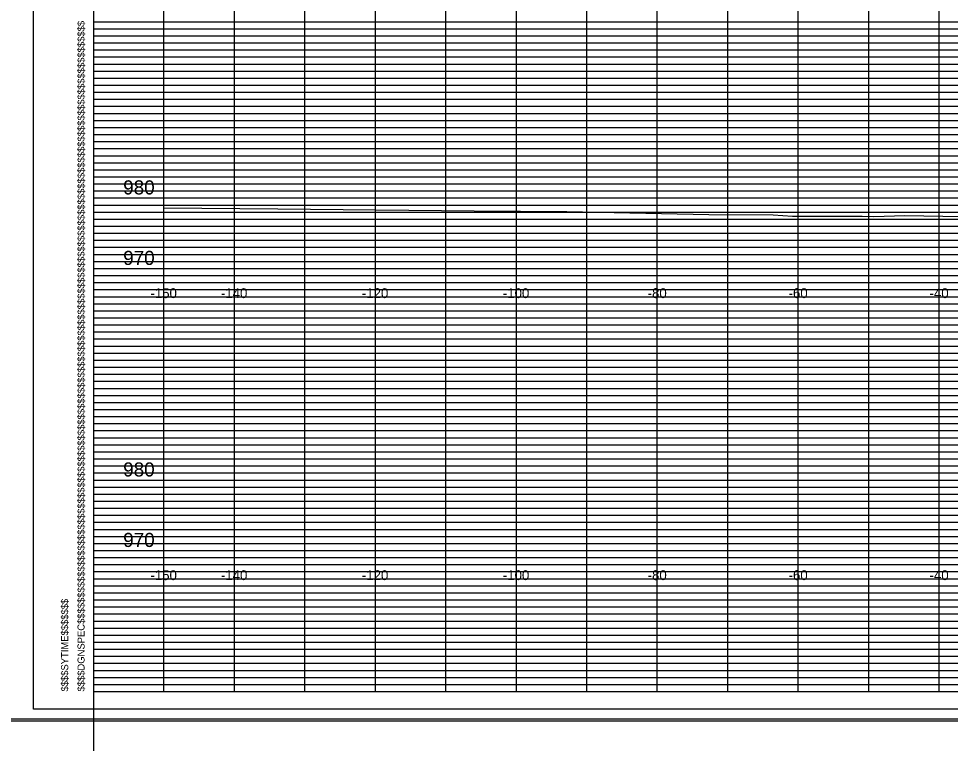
# Model space of a CAD drawing. Extents: x 2313580 to 2322968, y 282099 to 303247.
# Drawn here: x 2315288.3 to 2315420.5, y 285088.8 to 285191.6 of the extents above; entities that cross this region are included whole.
import ezdxf

# ---------------------------------------------------------------- set-up
doc = ezdxf.new("R2010")
doc.units = 0
for name, color, linetype in [('DESIGN - SCRATCH - User 1', 7, 'Continuous'), ('DESIGN - SHEET - Corner Text', 7, 'Continuous'), ('DESIGN - SHEET - Light Grid', 7, 'Continuous'), ('DESIGN - SHEET - Linework', 7, 'Continuous'), ('DESIGN - SHEET - Plot Shape', 7, 'Continuous'), ('DESIGN - TYPICAL - Text', 7, 'Continuous'), ('SURVEY - GROUND - Top of Ground', 7, 'Continuous')]:
    doc.layers.add(name, color=color, linetype=linetype)

msp = doc.modelspace()

# ---------------------------------------------------------------- linework, layer by layer
at = {"layer": 'DESIGN - SCRATCH - User 1'}
msp.add_line((2315298.88, 287582.67), (2315298.88, 284487.81), dxfattribs=at)
at = {"layer": 'DESIGN - SHEET - Light Grid'}
for p, q in [((2315298.88, 285191.13), (2315378.88, 285191.13)), ((2315378.88, 285191.13), (2315458.88, 285191.13)), ((2315298.88, 285190.13), (2315378.88, 285190.13)), ((2315378.88, 285190.13), (2315458.88, 285190.13)), ((2315298.88, 285189.13), (2315378.88, 285189.13)), ((2315378.88, 285189.13), (2315458.88, 285189.13)), ((2315298.88, 285188.13), (2315378.88, 285188.13)), ((2315298.88, 285187.13), (2315378.88, 285187.13)), ((2315378.88, 285188.13), (2315458.88, 285188.13)), ((2315378.88, 285187.13), (2315458.88, 285187.13)), ((2315298.88, 285185.13), (2315378.88, 285185.13)), ((2315378.88, 285185.13), (2315458.88, 285185.13)), ((2315298.88, 285184.13), (2315378.88, 285184.13)), ((2315298.88, 285183.13), (2315378.88, 285183.13)), ((2315378.88, 285184.13), (2315458.88, 285184.13)), ((2315378.88, 285183.13), (2315458.88, 285183.13)), ((2315298.88, 285182.13), (2315378.88, 285182.13)), ((2315378.88, 285182.13), (2315458.88, 285182.13)), ((2315298.88, 285181.13), (2315378.88, 285181.13)), ((2315378.88, 285181.13), (2315458.88, 285181.13)), ((2315298.88, 285180.13), (2315378.88, 285180.13)), ((2315298.88, 285179.13), (2315378.88, 285179.13)), ((2315378.88, 285180.13), (2315458.88, 285180.13)), ((2315378.88, 285179.13), (2315458.88, 285179.13)), ((2315298.88, 285178.13), (2315378.88, 285178.13)), ((2315378.88, 285178.13), (2315458.88, 285178.13)), ((2315298.88, 285177.13), (2315378.88, 285177.13)), ((2315378.88, 285177.13), (2315458.88, 285177.13)), ((2315298.88, 285175.13), (2315378.88, 285175.13)), ((2315378.88, 285175.13), (2315458.88, 285175.13)), ((2315298.88, 285174.13), (2315378.88, 285174.13)), ((2315378.88, 285174.13), (2315458.88, 285174.13)), ((2315298.88, 285173.13), (2315378.88, 285173.13)), ((2315378.88, 285173.13), (2315458.88, 285173.13)), ((2315298.88, 285172.13), (2315378.88, 285172.13)), ((2315298.88, 285171.13), (2315378.88, 285171.13)), ((2315378.88, 285172.13), (2315458.88, 285172.13)), ((2315378.88, 285171.13), (2315458.88, 285171.13)), ((2315298.88, 285170.13), (2315378.88, 285170.13)), ((2315378.88, 285170.13), (2315458.88, 285170.13)), ((2315298.88, 285169.13), (2315378.88, 285169.13)), ((2315378.88, 285169.13), (2315458.88, 285169.13)), ((2315298.88, 285168.13), (2315378.88, 285168.13)), ((2315298.88, 285167.13), (2315378.88, 285167.13)), ((2315378.88, 285168.13), (2315458.88, 285168.13)), ((2315378.88, 285167.13), (2315458.88, 285167.13)), ((2315298.88, 285165.13), (2315378.88, 285165.13)), ((2315378.88, 285165.13), (2315458.88, 285165.13)), ((2315298.88, 285164.13), (2315378.88, 285164.13)), ((2315298.88, 285163.13), (2315378.88, 285163.13)), ((2315378.88, 285164.13), (2315458.88, 285164.13)), ((2315378.88, 285163.13), (2315458.88, 285163.13)), ((2315298.88, 285162.13), (2315378.88, 285162.13)), ((2315378.88, 285162.13), (2315458.88, 285162.13)), ((2315298.88, 285161.13), (2315378.88, 285161.13)), ((2315378.88, 285161.13), (2315458.88, 285161.13)), ((2315298.88, 285160.13), (2315378.88, 285160.13)), ((2315298.88, 285159.13), (2315378.88, 285159.13)), ((2315378.88, 285160.13), (2315458.88, 285160.13)), ((2315378.88, 285159.13), (2315458.88, 285159.13)), ((2315298.88, 285158.13), (2315378.88, 285158.13)), ((2315378.88, 285158.13), (2315458.88, 285158.13)), ((2315298.88, 285157.13), (2315378.88, 285157.13)), ((2315378.88, 285157.13), (2315458.88, 285157.13)), ((2315298.88, 285155.13), (2315378.88, 285155.13)), ((2315378.88, 285155.13), (2315458.88, 285155.13)), ((2315298.88, 285154.13), (2315378.88, 285154.13)), ((2315378.88, 285154.13), (2315458.88, 285154.13)), ((2315298.88, 285153.13), (2315378.88, 285153.13)), ((2315378.88, 285153.13), (2315458.88, 285153.13)), ((2315298.88, 285152.13), (2315378.88, 285152.13)), ((2315298.88, 285151.13), (2315378.88, 285151.13)), ((2315378.88, 285152.13), (2315458.88, 285152.13)), ((2315378.88, 285151.13), (2315458.88, 285151.13)), ((2315298.88, 285150.13), (2315378.88, 285150.13)), ((2315378.88, 285150.13), (2315458.88, 285150.13)), ((2315298.88, 285149.13), (2315378.88, 285149.13)), ((2315378.88, 285149.13), (2315458.88, 285149.13)), ((2315298.88, 285148.13), (2315378.88, 285148.13)), ((2315378.88, 285148.13), (2315458.88, 285148.13)), ((2315298.88, 285147.13), (2315378.88, 285147.13)), ((2315378.88, 285147.13), (2315458.88, 285147.13)), ((2315298.88, 285145.13), (2315378.88, 285145.13)), ((2315378.88, 285145.13), (2315458.88, 285145.13)), ((2315298.88, 285144.13), (2315378.88, 285144.13)), ((2315378.88, 285144.13), (2315458.88, 285144.13)), ((2315298.88, 285143.13), (2315378.88, 285143.13)), ((2315298.88, 285142.13), (2315378.88, 285142.13)), ((2315378.88, 285143.13), (2315458.88, 285143.13)), ((2315378.88, 285142.13), (2315458.88, 285142.13)), ((2315298.88, 285141.13), (2315378.88, 285141.13)), ((2315378.88, 285141.13), (2315458.88, 285141.13)), ((2315298.88, 285140.13), (2315378.88, 285140.13)), ((2315378.88, 285140.13), (2315458.88, 285140.13)), ((2315298.88, 285139.13), (2315378.88, 285139.13)), ((2315298.88, 285138.13), (2315378.88, 285138.13)), ((2315378.88, 285139.13), (2315458.88, 285139.13)), ((2315378.88, 285138.13), (2315458.88, 285138.13)), ((2315298.88, 285137.13), (2315378.88, 285137.13)), ((2315378.88, 285137.13), (2315458.88, 285137.13)), ((2315298.88, 285135.13), (2315378.88, 285135.13)), ((2315298.88, 285134.13), (2315378.88, 285134.13)), ((2315378.88, 285135.13), (2315458.88, 285135.13)), ((2315378.88, 285134.13), (2315458.88, 285134.13)), ((2315298.88, 285133.13), (2315378.88, 285133.13)), ((2315378.88, 285133.13), (2315458.88, 285133.13)), ((2315298.88, 285132.13), (2315378.88, 285132.13)), ((2315378.88, 285132.13), (2315458.88, 285132.13)), ((2315298.88, 285131.13), (2315378.88, 285131.13)), ((2315298.88, 285130.13), (2315378.88, 285130.13)), ((2315378.88, 285131.13), (2315458.88, 285131.13)), ((2315378.88, 285130.13), (2315458.88, 285130.13)), ((2315298.88, 285129.13), (2315378.88, 285129.13)), ((2315378.88, 285129.13), (2315458.88, 285129.13)), ((2315298.88, 285128.13), (2315378.88, 285128.13)), ((2315378.88, 285128.13), (2315458.88, 285128.13)), ((2315298.88, 285127.13), (2315378.88, 285127.13)), ((2315378.88, 285127.13), (2315458.88, 285127.13)), ((2315298.88, 285125.13), (2315378.88, 285125.13)), ((2315378.88, 285125.13), (2315458.88, 285125.13)), ((2315298.88, 285124.13), (2315378.88, 285124.13)), ((2315378.88, 285124.13), (2315458.88, 285124.13)), ((2315298.88, 285123.13), (2315378.88, 285123.13)), ((2315298.88, 285122.13), (2315378.88, 285122.13)), ((2315378.88, 285123.13), (2315458.88, 285123.13)), ((2315378.88, 285122.13), (2315458.88, 285122.13)), ((2315298.88, 285121.13), (2315378.88, 285121.13)), ((2315378.88, 285121.13), (2315458.88, 285121.13)), ((2315298.88, 285120.13), (2315378.88, 285120.13)), ((2315378.88, 285120.13), (2315458.88, 285120.13)), ((2315298.88, 285119.13), (2315378.88, 285119.13)), ((2315298.88, 285118.13), (2315378.88, 285118.13)), ((2315378.88, 285119.13), (2315458.88, 285119.13)), ((2315378.88, 285118.13), (2315458.88, 285118.13)), ((2315298.88, 285117.13), (2315378.88, 285117.13)), ((2315378.88, 285117.13), (2315458.88, 285117.13)), ((2315298.88, 285115.13), (2315378.88, 285115.13)), ((2315298.88, 285114.13), (2315378.88, 285114.13)), ((2315378.88, 285115.13), (2315458.88, 285115.13)), ((2315378.88, 285114.13), (2315458.88, 285114.13)), ((2315298.88, 285113.13), (2315378.88, 285113.13)), ((2315378.88, 285113.13), (2315458.88, 285113.13)), ((2315298.88, 285112.13), (2315378.88, 285112.13)), ((2315378.88, 285112.13), (2315458.88, 285112.13)), ((2315298.88, 285111.13), (2315378.88, 285111.13)), ((2315378.88, 285111.13), (2315458.88, 285111.13)), ((2315298.88, 285110.13), (2315378.88, 285110.13)), ((2315298.88, 285109.13), (2315378.88, 285109.13)), ((2315378.88, 285110.13), (2315458.88, 285110.13)), ((2315378.88, 285109.13), (2315458.88, 285109.13)), ((2315298.88, 285108.13), (2315378.88, 285108.13)), ((2315378.88, 285108.13), (2315458.88, 285108.13)), ((2315298.88, 285107.13), (2315378.88, 285107.13)), ((2315378.88, 285107.13), (2315458.88, 285107.13)), ((2315298.88, 285105.13), (2315378.88, 285105.13)), ((2315378.88, 285105.13), (2315458.88, 285105.13)), ((2315298.88, 285104.13), (2315378.88, 285104.13)), ((2315378.88, 285104.13), (2315458.88, 285104.13)), ((2315298.88, 285103.13), (2315378.88, 285103.13)), ((2315378.88, 285103.13), (2315458.88, 285103.13)), ((2315298.88, 285102.13), (2315378.88, 285102.13)), ((2315298.88, 285101.13), (2315378.88, 285101.13)), ((2315378.88, 285102.13), (2315458.88, 285102.13)), ((2315378.88, 285101.13), (2315458.88, 285101.13)), ((2315298.88, 285100.13), (2315378.88, 285100.13)), ((2315378.88, 285100.13), (2315458.88, 285100.13)), ((2315298.88, 285099.13), (2315378.88, 285099.13)), ((2315378.88, 285099.13), (2315458.88, 285099.13)), ((2315298.88, 285098.13), (2315378.88, 285098.13)), ((2315298.88, 285097.13), (2315378.88, 285097.13)), ((2315378.88, 285098.13), (2315458.88, 285098.13)), ((2315378.88, 285097.13), (2315458.88, 285097.13))]:
    msp.add_line(p, q, dxfattribs=at)
at = {"layer": 'DESIGN - SHEET - Linework'}
for p, q in [((2315308.88, 285096.13), (2315308.88, 285306.13)), ((2315318.88, 285096.13), (2315318.88, 285306.13)), ((2315328.88, 285096.13), (2315328.88, 285306.13)), ((2315338.88, 285096.13), (2315338.88, 285306.13)), ((2315348.88, 285096.13), (2315348.88, 285306.13)), ((2315358.88, 285096.13), (2315358.88, 285306.13)), ((2315368.88, 285096.13), (2315368.88, 285306.13)), ((2315378.88, 285096.13), (2315378.88, 285306.13)), ((2315388.88, 285096.13), (2315388.88, 285306.13)), ((2315398.88, 285096.13), (2315398.88, 285306.13)), ((2315408.88, 285096.13), (2315408.88, 285306.13)), ((2315418.88, 285096.13), (2315418.88, 285306.13)), ((2315298.88, 285186.13), (2315618.88, 285186.13)), ((2315298.88, 285176.13), (2315618.88, 285176.13)), ((2315298.88, 285166.13), (2315618.88, 285166.13)), ((2315308.88, 285156.13), (2315308.88, 285166.13)), ((2315298.88, 285156.13), (2315618.88, 285156.13)), ((2315308.88, 285156.13), (2315608.88, 285156.13)), ((2315298.88, 285146.13), (2315618.88, 285146.13)), ((2315298.88, 285136.13), (2315618.88, 285136.13)), ((2315298.88, 285126.13), (2315618.88, 285126.13)), ((2315308.88, 285116.13), (2315308.88, 285126.13)), ((2315298.88, 285116.13), (2315618.88, 285116.13)), ((2315308.88, 285116.13), (2315608.88, 285116.13)), ((2315298.88, 285106.13), (2315618.88, 285106.13)), ((2315280.65, 285091.99), (2315621.05, 285091.99))]:
    msp.add_line(p, q, dxfattribs=at)
msp.add_lwpolyline([(2315298.88, 285306.13), (2315298.88, 285096.13), (2315618.88, 285096.13), (2315618.88, 285306.13), (2315298.88, 285306.13)], dxfattribs=at)
at = {"layer": 'DESIGN - SHEET - Plot Shape'}
for points in [[(2315280.85, 285310.07), (2315620.85, 285310.07), (2315620.85, 285092.19), (2315280.85, 285092.19)], [(2315290.38, 285306.13), (2315618.88, 285306.13), (2315618.88, 285093.63), (2315290.38, 285093.63)]]:
    msp.add_lwpolyline(points, close=True, dxfattribs=at)
at = {"layer": 'SURVEY - GROUND - Top of Ground'}
msp.add_lwpolyline([(2315308.88, 285164.75), (2315325.05, 285164.59), (2315352.89, 285164.32), (2315366.06, 285164.23), (2315386.19, 285163.8), (2315395.32, 285163.72), (2315398.07, 285163.55), (2315407.95, 285163.54), (2315409.61, 285163.52), (2315414.02, 285163.63), (2315422.11, 285163.48)], dxfattribs=at)

# ---------------------------------------------------------------- texts
at = {"layer": 'DESIGN - SHEET - Corner Text'}
for s, height, p in [('$$$$DGNSPEC$$$$$$$$$$$$$$$$$$$$$$$$$$$$$$$$$$$$$$$$$$$$$$$$$$$$$$$$$$$$$$$$$$$$$$$$$$$$$$$$$$$$$$$$$$$$$$$$$$$$$$$$$$$$$$$$$$$', 1.00002, (2315297.62, 285096.13)), ('$$$$SYTIME$$$$$$$', 1, (2315295.3, 285096.13))]:
    msp.add_text(s, height=height, rotation=90, dxfattribs=at).set_placement(p)
at = {"layer": 'DESIGN - SHEET - Linework'}
for p in [(2315308.88, 285156.13), (2315308.88, 285116.13)]:
    msp.add_text('-', height=0.0001, dxfattribs=at).set_placement(p)
at = {"layer": 'DESIGN - TYPICAL - Text'}
for s, height, p in [('980', 2, (2315303.1, 285166.63)), ('970', 2, (2315303.1, 285156.63)), ('-150', 1.4, (2315306.97, 285151.93)), ('-140', 1.4, (2315316.97, 285151.93)), ('-120', 1.4, (2315336.97, 285151.93)), ('-100', 1.4, (2315356.97, 285151.93)), ('-80', 1.4, (2315377.51, 285151.93)), ('-60', 1.4, (2315397.51, 285151.93)), ('-40', 1.4, (2315417.51, 285151.93)), ('980', 2, (2315303.1, 285126.63)), ('970', 2, (2315303.1, 285116.63)), ('-150', 1.4, (2315306.97, 285111.93)), ('-140', 1.4, (2315316.97, 285111.93)), ('-120', 1.4, (2315336.97, 285111.93)), ('-100', 1.4, (2315356.97, 285111.93)), ('-80', 1.4, (2315377.51, 285111.93)), ('-60', 1.4, (2315397.51, 285111.93)), ('-40', 1.4, (2315417.51, 285111.93))]:
    msp.add_text(s, height=height, dxfattribs=at).set_placement(p)

doc.saveas('drawing.dxf')
